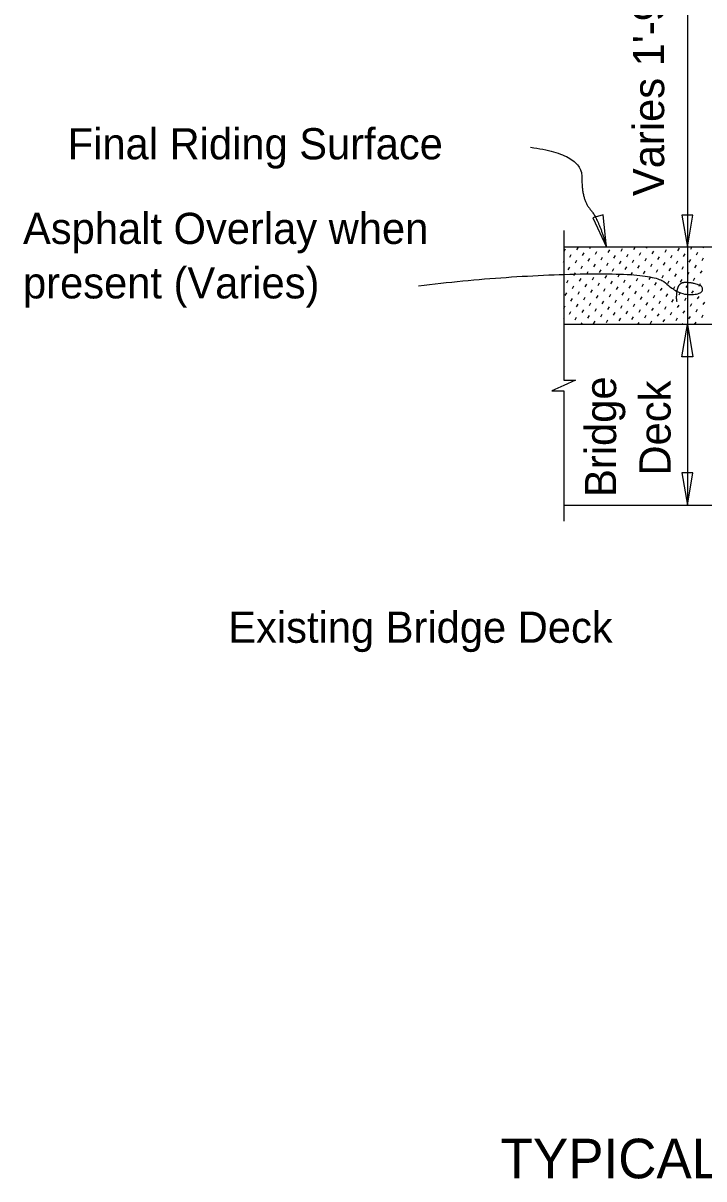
# Model space of a CAD drawing. Extents: x 21629.5 to 21698.8, y 56199.4 to 56237.6.
# Drawn here: x 21630.75 to 21635.16, y 56220.84 to 56228.32 of the extents above; entities that cross this region are included whole.
import ezdxf

# ---------------------------------------------------------------- set-up
doc = ezdxf.new("R2010")
doc.units = 0
for name, color, linetype in [('Dimension', 7, 'Continuous'), ('ExistSuperStruct', 7, 'Continuous'), ('Miscellaneous', 7, 'Continuous'), ('TextStructures', 7, 'Continuous')]:
    doc.layers.add(name, color=color, linetype=linetype)

msp = doc.modelspace()

# ---------------------------------------------------------------- linework, layer by layer
at = {"layer": 'Dimension'}
msp.add_line((21635.0527, 56232.202), (21635.0527, 56225.2019), dxfattribs=at)
for points in [[(21634.5301, 56226.8686), (21634.5088, 56227.0787), (21634.4408, 56227.06)], [(21635.0528, 56226.8686), (21635.0881, 56227.0769), (21635.0176, 56227.0769)], [(21635.0527, 56226.3686), (21635.088, 56226.1603), (21635.0174, 56226.1603)], [(21635.0527, 56225.2019), (21635.088, 56225.4102), (21635.0174, 56225.4102)]]:
    msp.add_lwpolyline(points, close=True, dxfattribs=at)
msp.add_lwpolyline([(21634.2525, 56226.9778), (21634.2525, 56226.0088), (21634.33, 56226.0088), (21634.2525, 56225.9751), (21634.175, 56225.9413), (21634.2525, 56225.9413), (21634.2525, 56225.0986)], dxfattribs=at)
for points in [[(21634.0383, 56227.5151), (21634.3722, 56227.4708), (21634.3685, 56227.1758), (21634.4791, 56227.0538), (21634.5301, 56226.8686)], [(21633.313, 56226.6199), (21633.8458, 56226.6844), (21634.8358, 56226.7072), (21634.9775, 56226.5767), (21635.0824, 56226.5583), (21635.1518, 56226.5767), (21635.1518, 56226.6178), (21635.081, 56226.6405), (21634.9945, 56226.6405), (21634.9774, 56226.5402), (21634.9845, 56226.5181)]]:
    msp.add_open_spline(points, degree=2, dxfattribs=at)
at = {"layer": 'ExistSuperStruct'}
for p, q in [((21638.1857, 56226.3686), (21634.2524, 56226.3686)), ((21634.2524, 56225.2019), (21640.8941, 56225.2019))]:
    msp.add_line(p, q, dxfattribs=at)
at = {"layer": 'Miscellaneous'}
for p, q in [((21638.2445, 56226.8686), (21634.2524, 56226.8686)), ((21634.2552, 56226.8421), (21634.2649, 56226.8589)), ((21634.3381, 56226.8518), (21634.3478, 56226.8686)), ((21634.4211, 56226.8616), (21634.4251, 56226.8686)), ((21634.4577, 56226.825), (21634.4674, 56226.8418)), ((21634.5406, 56226.8347), (21634.5503, 56226.8515)), ((21634.6235, 56226.8444), (21634.6333, 56226.8612)), ((21634.7065, 56226.8541), (21634.7149, 56226.8686)), ((21634.7894, 56226.8639), (21634.7922, 56226.8686)), ((21634.826, 56226.8272), (21634.8358, 56226.844)), ((21634.909, 56226.837), (21634.9187, 56226.8538)), ((21634.9919, 56226.8467), (21635.0016, 56226.8635)), ((21635.0748, 56226.8564), (21635.0819, 56226.8686)), ((21635.1578, 56226.8661), (21635.1592, 56226.8686)), ((21634.2524, 56226.7712), (21634.2552, 56226.776)), ((21634.2918, 56226.8055), (21634.3015, 56226.8223)), ((21634.3284, 56226.7689), (21634.3381, 56226.7857)), ((21634.3747, 56226.8152), (21634.3845, 56226.832)), ((21634.4113, 56226.7786), (21634.4211, 56226.7954)), ((21634.4943, 56226.7884), (21634.504, 56226.8052)), ((21634.5309, 56226.7517), (21634.5406, 56226.7685)), ((21634.5772, 56226.7981), (21634.5869, 56226.8149)), ((21634.6138, 56226.7615), (21634.6235, 56226.7783)), ((21634.6602, 56226.8078), (21634.6699, 56226.8246)), ((21634.6968, 56226.7712), (21634.7065, 56226.788)), ((21634.7431, 56226.8175), (21634.7528, 56226.8343)), ((21634.7797, 56226.7809), (21634.7894, 56226.7977)), ((21634.8626, 56226.7906), (21634.8724, 56226.8074)), ((21634.8992, 56226.754), (21634.909, 56226.7708)), ((21634.9456, 56226.8004), (21634.9553, 56226.8172)), ((21634.9822, 56226.7638), (21634.9919, 56226.7805)), ((21635.0285, 56226.8101), (21635.0382, 56226.8269)), ((21635.0651, 56226.7735), (21635.0748, 56226.7903)), ((21635.1114, 56226.8198), (21635.1212, 56226.8366)), ((21635.1481, 56226.7832), (21635.1578, 56226.8)), ((21634.2821, 56226.7226), (21634.2918, 56226.7394)), ((21634.3187, 56226.686), (21634.3284, 56226.7028)), ((21634.365, 56226.7323), (21634.3747, 56226.7491)), ((21634.4016, 56226.6957), (21634.4113, 56226.7125)), ((21634.4479, 56226.742), (21634.4577, 56226.7588)), ((21634.4846, 56226.7054), (21634.4943, 56226.7222)), ((21634.5675, 56226.7151), (21634.5772, 56226.7319)), ((21634.6041, 56226.6785), (21634.6138, 56226.6953)), ((21634.6504, 56226.7249), (21634.6602, 56226.7417)), ((21634.687, 56226.6883), (21634.6968, 56226.7051)), ((21634.7334, 56226.7346), (21634.7431, 56226.7514)), ((21634.77, 56226.698), (21634.7797, 56226.7148)), ((21634.8163, 56226.7443), (21634.826, 56226.7611)), ((21634.8529, 56226.7077), (21634.8626, 56226.7245)), ((21634.9359, 56226.7174), (21634.9456, 56226.7342)), ((21634.9725, 56226.6808), (21634.9822, 56226.6976)), ((21635.0188, 56226.7271), (21635.0285, 56226.7439)), ((21635.0554, 56226.6905), (21635.0651, 56226.7073)), ((21635.1017, 56226.7369), (21635.1114, 56226.7537)), ((21635.1383, 56226.7003), (21635.1481, 56226.7171)), ((21634.2723, 56226.6396), (21634.2821, 56226.6564)), ((21634.309, 56226.603), (21634.3187, 56226.6198)), ((21634.3553, 56226.6494), (21634.365, 56226.6662)), ((21634.3919, 56226.6128), (21634.4016, 56226.6296)), ((21634.4382, 56226.6591), (21634.4479, 56226.6759)), ((21634.4748, 56226.6225), (21634.4846, 56226.6393)), ((21634.5212, 56226.6688), (21634.5309, 56226.6856)), ((21634.5578, 56226.6322), (21634.5675, 56226.649)), ((21634.6407, 56226.6419), (21634.6504, 56226.6587)), ((21634.6773, 56226.6053), (21634.687, 56226.6221)), ((21634.7236, 56226.6516), (21634.7334, 56226.6684)), ((21634.7603, 56226.615), (21634.77, 56226.6318)), ((21634.8066, 56226.6614), (21634.8163, 56226.6782)), ((21634.8432, 56226.6248), (21634.8529, 56226.6416)), ((21634.8895, 56226.6711), (21634.8992, 56226.6879)), ((21634.9261, 56226.6345), (21634.9359, 56226.6513)), ((21634.9627, 56226.5979), (21634.9725, 56226.6147)), ((21635.0091, 56226.6442), (21635.0188, 56226.661)), ((21635.0457, 56226.6076), (21635.0554, 56226.6244)), ((21635.092, 56226.6539), (21635.1017, 56226.6707)), ((21635.1286, 56226.6173), (21635.1383, 56226.6341)), ((21634.2626, 56226.5567), (21634.2723, 56226.5735)), ((21634.3456, 56226.5664), (21634.3553, 56226.5832)), ((21634.3822, 56226.5298), (21634.3919, 56226.5466)), ((21634.4285, 56226.5762), (21634.4382, 56226.5929)), ((21634.4651, 56226.5395), (21634.4748, 56226.5563)), ((21634.5114, 56226.5859), (21634.5212, 56226.6027)), ((21634.548, 56226.5493), (21634.5578, 56226.5661)), ((21634.5944, 56226.5956), (21634.6041, 56226.6124)), ((21634.631, 56226.559), (21634.6407, 56226.5758)), ((21634.6676, 56226.5224), (21634.6773, 56226.5392)), ((21634.7139, 56226.5687), (21634.7236, 56226.5855)), ((21634.7505, 56226.5321), (21634.7603, 56226.5489)), ((21634.7969, 56226.5784), (21634.8066, 56226.5952)), ((21634.8335, 56226.5418), (21634.8432, 56226.5586)), ((21634.8798, 56226.5882), (21634.8895, 56226.605)), ((21634.9164, 56226.5515), (21634.9261, 56226.5683)), ((21634.9993, 56226.5613), (21635.0091, 56226.5781)), ((21635.036, 56226.5247), (21635.0457, 56226.5415)), ((21635.0823, 56226.571), (21635.092, 56226.5878)), ((21635.1189, 56226.5344), (21635.1286, 56226.5512)), ((21634.2529, 56226.4738), (21634.2626, 56226.4906)), ((21634.2992, 56226.5201), (21634.309, 56226.5369)), ((21634.3358, 56226.4835), (21634.3456, 56226.5003)), ((21634.4188, 56226.4932), (21634.4285, 56226.51)), ((21634.4554, 56226.4566), (21634.4651, 56226.4734)), ((21634.5017, 56226.5029), (21634.5114, 56226.5197)), ((21634.5383, 56226.4663), (21634.548, 56226.4831)), ((21634.5847, 56226.5127), (21634.5944, 56226.5295)), ((21634.6213, 56226.4761), (21634.631, 56226.4928)), ((21634.7042, 56226.4858), (21634.7139, 56226.5026)), ((21634.7408, 56226.4492), (21634.7505, 56226.466)), ((21634.7871, 56226.4955), (21634.7969, 56226.5123)), ((21634.8237, 56226.4589), (21634.8335, 56226.4757)), ((21634.8701, 56226.5052), (21634.8798, 56226.522)), ((21634.9067, 56226.4686), (21634.9164, 56226.4854)), ((21634.953, 56226.5149), (21634.9627, 56226.5317)), ((21634.9896, 56226.4783), (21634.9993, 56226.4951)), ((21635.0726, 56226.4881), (21635.0823, 56226.5049)), ((21635.1092, 56226.4514), (21635.1189, 56226.4682)), ((21635.1555, 56226.4978), (21635.1652, 56226.5146)), ((21634.2524, 56226.4067), (21634.2529, 56226.4076)), ((21634.2895, 56226.4372), (21634.2992, 56226.454)), ((21634.3261, 56226.4006), (21634.3358, 56226.4173)), ((21634.3724, 56226.4469), (21634.3822, 56226.4637)), ((21634.4091, 56226.4103), (21634.4188, 56226.4271)), ((21634.4457, 56226.3737), (21634.4554, 56226.3905)), ((21634.492, 56226.42), (21634.5017, 56226.4368)), ((21634.5286, 56226.3834), (21634.5383, 56226.4002)), ((21634.5749, 56226.4297), (21634.5847, 56226.4465)), ((21634.6115, 56226.3931), (21634.6213, 56226.4099)), ((21634.6579, 56226.4394), (21634.6676, 56226.4562)), ((21634.6945, 56226.4028), (21634.7042, 56226.4196)), ((21634.7774, 56226.4126), (21634.7871, 56226.4294)), ((21634.814, 56226.376), (21634.8237, 56226.3927)), ((21634.8604, 56226.4223), (21634.8701, 56226.4391)), ((21634.897, 56226.3857), (21634.9067, 56226.4025)), ((21634.9433, 56226.432), (21634.953, 56226.4488)), ((21634.9799, 56226.3954), (21634.9896, 56226.4122)), ((21635.0262, 56226.4417), (21635.036, 56226.4585)), ((21635.0628, 56226.4051), (21635.0726, 56226.4219)), ((21635.1458, 56226.4148), (21635.1555, 56226.4316)), ((21634.2881, 56226.3686), (21634.2895, 56226.371)), ((21634.3654, 56226.3686), (21634.3724, 56226.3807)), ((21634.6551, 56226.3686), (21634.6579, 56226.3733)), ((21634.7324, 56226.3686), (21634.7408, 56226.383)), ((21635.0222, 56226.3686), (21635.0262, 56226.3756)), ((21635.0995, 56226.3686), (21635.1092, 56226.3853))]:
    msp.add_line(p, q, dxfattribs=at)

# ---------------------------------------------------------------- texts
at = {"layer": 'Dimension'}
for s, p in [('Bridge', (21634.5921, 56225.2544)), ('Deck', (21634.9441, 56225.3927))]:
    msp.add_text(s, height=0.2016, rotation=90, dxfattribs=at).set_placement(p)
msp.add_text('TYPICAL SECTION THRU RAILING ON BRIDGE DECK', height=0.256001, dxfattribs=at).set_placement((21633.8446, 56220.8486))
at = {"layer": 'TextStructures'}
msp.add_text('Varies 1\'-9" to 2\'-0"', height=0.2016, rotation=90, dxfattribs=at).set_placement((21634.9027, 56227.1997))
for s, p in [('Final Riding Surface', (21631.0433, 56227.4373)), ('Asphalt Overlay when ', (21630.7543, 56226.8901)), ('present (Varies)', (21630.7543, 56226.5381)), ('Existing Bridge Deck', (21632.0823, 56224.3113))]:
    msp.add_text(s, height=0.2016, dxfattribs=at).set_placement(p)

doc.saveas('drawing.dxf')
